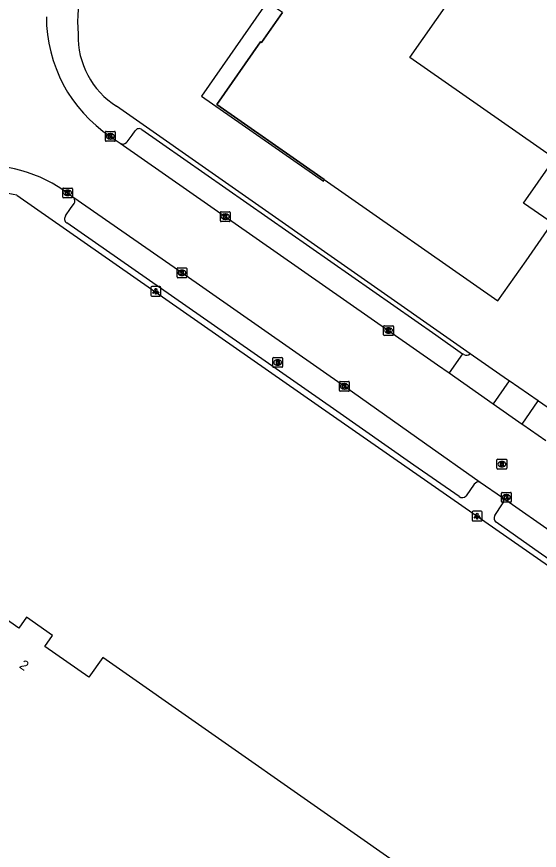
# Model space of a CAD drawing. Extents: x 155018 to 156648, y 383980 to 385733.
# Drawn here: x 155212.6 to 155265.9, y 385106.9 to 385192.1 of the extents above; entities that cross this region are included whole.
import ezdxf

# ---------------------------------------------------------------- set-up
doc = ezdxf.new("R2010")
doc.units = 0
for name, color, linetype in [('IMGEO_Brandkraan', 7, 'Continuous'), ('IMGEO_Kolk', 7, 'Continuous'), ('IMGEO_Lichtpunt', 7, 'Continuous'), ('IMGEO_Pand', 7, 'Continuous'), ('IMGEO_Pand_nummerreeks', 7, 'Continuous'), ('IMGEO_Pand_overbouw', 7, 'Continuous'), ('IMGEO_Rijbaan_lokaal_gesloten', 7, 'Continuous'), ('IMGEO_Rijbaan_lokaal_open', 7, 'Continuous'), ('IMGEO_Rioolput', 7, 'Continuous'), ('IMGEO_Voetpad_open', 7, 'Continuous')]:
    doc.layers.add(name, color=color, linetype=linetype)

msp = doc.modelspace()

# ---------------------------------------------------------------- linework, layer by layer
at = {"layer": 'IMGEO_Brandkraan'}
for p, q in [((155238.704, 385156.347), (155238.704, 385157.199)), ((155238.779, 385157.273), (155239.631, 385157.273)), ((155239.705, 385157.199), (155239.705, 385156.347)), ((155239.215, 385156.493), (155239.19, 385156.493)), ((155239.192, 385157.053), (155239.217, 385157.053)), ((155239.631, 385156.273), (155238.779, 385156.273))]:
    msp.add_line(p, q, dxfattribs=at)
for points in [[(155238.704, 385156.347), (155238.704, 385157.199)], [(155238.779, 385157.273), (155239.631, 385157.273)], [(155239.705, 385157.199), (155239.705, 385156.347)], [(155239.052, 385156.973), (155239.052, 385156.573), (155239.265, 385156.573)], [(155239.283, 385156.973), (155239.052, 385156.973)], [(155239.231, 385156.892), (155239.177, 385156.892), (155239.177, 385156.816)], [(155239.177, 385156.816), (155239.23, 385156.816)], [(155239.239, 385156.74), (155239.177, 385156.74), (155239.177, 385156.659)], [(155239.177, 385156.659), (155239.239, 385156.659)], [(155239.631, 385156.273), (155238.779, 385156.273)]]:
    msp.add_lwpolyline(points, dxfattribs=at)
for centre, radius, start, end in [((155238.781, 385157.197), 0.0765, 91.55205, 178.44795), ((155238.781, 385157.197), 0.0765, 91.55205, 178.44795), ((155239.629, 385157.197), 0.0765, 1.55205, 88.44795), ((155239.629, 385157.197), 0.0765, 1.55205, 88.44795), ((155238.781, 385156.349), 0.0765, 181.55205, 268.44795), ((155238.781, 385156.349), 0.0765, 181.55205, 268.44795), ((155239.232, 385156.854), 0.0379, 267.82845, 90.93552), ((155239.24, 385156.699), 0.0404, 269.87594, 90.50774), ((155239.271, 385156.824), 0.251, 268.66757, 293.53466), ((155239.287, 385156.828), 0.145, 59.4692, 91.53667), ((155239.312, 385156.875), 0.0922, 285.51372, 58.15012), ((155239.317, 385156.683), 0.105, 301.31148, 78.98903), ((155239.629, 385156.349), 0.0765, 271.55205, 358.44795), ((155239.629, 385156.349), 0.0765, 271.55205, 358.44795)]:
    msp.add_arc(centre, radius, start, end, dxfattribs=at)
for centre, major_axis, ratio, start_param, end_param in [((155239.191, 385156.773), (-0.387, 0.002), 0.722429, 4.712389, 7.853982), ((155239.216, 385156.773), (-0.39, 0.002), 0.717154, 1.570796, 4.712389)]:
    msp.add_ellipse(centre, major_axis=major_axis, ratio=ratio, start_param=start_param, end_param=end_param, dxfattribs=at)
at = {"layer": 'IMGEO_Kolk'}
for p, q in [((155221.621, 385179.436), (155221.621, 385180.288)), ((155221.696, 385180.362), (155222.548, 385180.362)), ((155222.622, 385180.288), (155222.622, 385179.436)), ((155222.548, 385179.362), (155221.696, 385179.362)), ((155222.132, 385179.582), (155222.107, 385179.582)), ((155222.109, 385180.142), (155222.134, 385180.142)), ((155217.256, 385173.657), (155217.256, 385174.509)), ((155217.331, 385174.583), (155218.183, 385174.583)), ((155217.744, 385174.363), (155217.769, 385174.363)), ((155218.257, 385174.509), (155218.257, 385173.657)), ((155218.183, 385173.583), (155217.331, 385173.583)), ((155217.767, 385173.803), (155217.742, 385173.803)), ((155233.352, 385171.233), (155233.352, 385172.085)), ((155233.427, 385172.159), (155234.279, 385172.159)), ((155233.84, 385171.939), (155233.865, 385171.939)), ((155234.353, 385172.085), (155234.353, 385171.233)), ((155234.279, 385171.159), (155233.427, 385171.159)), ((155233.863, 385171.379), (155233.838, 385171.379)), ((155228.932, 385165.499), (155228.932, 385166.351)), ((155229.007, 385166.425), (155229.859, 385166.425)), ((155229.42, 385166.205), (155229.445, 385166.205)), ((155229.933, 385166.351), (155229.933, 385165.499)), ((155229.859, 385165.425), (155229.007, 385165.425)), ((155229.443, 385165.645), (155229.418, 385165.645)), ((155250.022, 385159.597), (155250.022, 385160.449)), ((155250.097, 385160.523), (155250.949, 385160.523)), ((155250.533, 385159.743), (155250.508, 385159.743)), ((155250.51, 385160.303), (155250.535, 385160.303)), ((155251.023, 385160.449), (155251.023, 385159.597)), ((155250.949, 385159.523), (155250.097, 385159.523)), ((155245.512, 385153.905), (155245.512, 385154.757)), ((155245.587, 385154.831), (155246.439, 385154.831)), ((155246.513, 385154.757), (155246.513, 385153.905)), ((155246.439, 385153.831), (155245.587, 385153.831)), ((155246.023, 385154.051), (155245.998, 385154.051)), ((155246, 385154.611), (155246.025, 385154.611)), ((155262.05, 385142.569), (155262.05, 385143.421)), ((155262.125, 385143.495), (155262.977, 385143.495)), ((155262.561, 385142.715), (155262.536, 385142.715)), ((155262.538, 385143.275), (155262.563, 385143.275)), ((155263.051, 385143.421), (155263.051, 385142.569)), ((155262.977, 385142.495), (155262.125, 385142.495))]:
    msp.add_line(p, q, dxfattribs=at)
for points in [[(155221.621, 385179.436), (155221.621, 385180.288)], [(155221.696, 385180.362), (155222.548, 385180.362)], [(155222.622, 385180.288), (155222.622, 385179.436)], [(155222.548, 385179.362), (155221.696, 385179.362)], [(155221.942, 385180.062), (155222.065, 385180.062), (155222.065, 385179.911), (155222.195, 385180.062), (155222.359, 385180.062), (155222.213, 385179.911), (155222.366, 385179.662), (155222.214, 385179.662), (155222.129, 385179.826), (155222.065, 385179.759), (155222.065, 385179.662), (155221.942, 385179.662), (155221.942, 385180.062)], [(155217.256, 385173.657), (155217.256, 385174.509)], [(155217.331, 385174.583), (155218.183, 385174.583)], [(155217.577, 385174.283), (155217.7, 385174.283), (155217.7, 385174.132), (155217.83, 385174.283), (155217.994, 385174.283), (155217.848, 385174.132), (155218.001, 385173.883), (155217.849, 385173.883), (155217.764, 385174.047), (155217.7, 385173.98), (155217.7, 385173.883), (155217.577, 385173.883), (155217.577, 385174.283)], [(155218.257, 385174.509), (155218.257, 385173.657)], [(155218.183, 385173.583), (155217.331, 385173.583)], [(155233.352, 385171.233), (155233.352, 385172.085)], [(155233.427, 385172.159), (155234.279, 385172.159)], [(155233.673, 385171.859), (155233.796, 385171.859), (155233.796, 385171.708), (155233.926, 385171.859), (155234.09, 385171.859), (155233.944, 385171.708), (155234.097, 385171.459), (155233.945, 385171.459), (155233.86, 385171.623), (155233.796, 385171.556), (155233.796, 385171.459), (155233.673, 385171.459), (155233.673, 385171.859)], [(155234.353, 385172.085), (155234.353, 385171.233)], [(155234.279, 385171.159), (155233.427, 385171.159)], [(155228.932, 385165.499), (155228.932, 385166.351)], [(155229.007, 385166.425), (155229.859, 385166.425)], [(155229.253, 385166.125), (155229.376, 385166.125), (155229.376, 385165.974), (155229.506, 385166.125), (155229.67, 385166.125), (155229.524, 385165.974), (155229.677, 385165.725), (155229.525, 385165.725), (155229.44, 385165.889), (155229.376, 385165.822), (155229.376, 385165.725), (155229.253, 385165.725), (155229.253, 385166.125)], [(155229.933, 385166.351), (155229.933, 385165.499)], [(155229.859, 385165.425), (155229.007, 385165.425)], [(155250.022, 385159.597), (155250.022, 385160.449)], [(155250.097, 385160.523), (155250.949, 385160.523)], [(155250.343, 385160.223), (155250.466, 385160.223), (155250.466, 385160.072), (155250.596, 385160.223), (155250.76, 385160.223), (155250.614, 385160.072), (155250.767, 385159.823), (155250.615, 385159.823), (155250.53, 385159.987), (155250.466, 385159.92), (155250.466, 385159.823), (155250.343, 385159.823), (155250.343, 385160.223)], [(155251.023, 385160.449), (155251.023, 385159.597)], [(155250.949, 385159.523), (155250.097, 385159.523)], [(155245.512, 385153.905), (155245.512, 385154.757)], [(155245.587, 385154.831), (155246.439, 385154.831)], [(155246.513, 385154.757), (155246.513, 385153.905)], [(155246.439, 385153.831), (155245.587, 385153.831)], [(155245.833, 385154.531), (155245.956, 385154.531), (155245.956, 385154.38), (155246.086, 385154.531), (155246.25, 385154.531), (155246.104, 385154.38), (155246.257, 385154.131), (155246.105, 385154.131), (155246.02, 385154.295), (155245.956, 385154.228), (155245.956, 385154.131), (155245.833, 385154.131), (155245.833, 385154.531)], [(155262.05, 385142.569), (155262.05, 385143.421)], [(155262.125, 385143.495), (155262.977, 385143.495)], [(155262.371, 385143.195), (155262.494, 385143.195), (155262.494, 385143.044), (155262.624, 385143.195), (155262.788, 385143.195), (155262.642, 385143.044), (155262.795, 385142.795), (155262.643, 385142.795), (155262.558, 385142.959), (155262.494, 385142.892), (155262.494, 385142.795), (155262.371, 385142.795), (155262.371, 385143.195)], [(155263.051, 385143.421), (155263.051, 385142.569)], [(155262.977, 385142.495), (155262.125, 385142.495)]]:
    msp.add_lwpolyline(points, dxfattribs=at)
for centre, start, end in [((155221.698, 385180.286), 91.55205, 178.44795), ((155221.698, 385180.286), 91.55205, 178.44795), ((155222.546, 385180.286), 1.55205, 88.44795), ((155222.546, 385180.286), 1.55205, 88.44795), ((155221.698, 385179.438), 181.55205, 268.44795), ((155221.698, 385179.438), 181.55205, 268.44795), ((155222.546, 385179.438), 271.55205, 358.44795), ((155222.546, 385179.438), 271.55205, 358.44795), ((155217.333, 385174.507), 91.55205, 178.44795), ((155217.333, 385174.507), 91.55205, 178.44795), ((155218.181, 385174.507), 1.55205, 88.44795), ((155218.181, 385174.507), 1.55205, 88.44795), ((155217.333, 385173.659), 181.55205, 268.44795), ((155217.333, 385173.659), 181.55205, 268.44795), ((155218.181, 385173.659), 271.55205, 358.44795), ((155218.181, 385173.659), 271.55205, 358.44795), ((155233.429, 385172.083), 91.55205, 178.44795), ((155233.429, 385172.083), 91.55205, 178.44795), ((155234.277, 385172.083), 1.55205, 88.44795), ((155234.277, 385172.083), 1.55205, 88.44795), ((155233.429, 385171.235), 181.55205, 268.44795), ((155233.429, 385171.235), 181.55205, 268.44795), ((155234.277, 385171.235), 271.55205, 358.44795), ((155234.277, 385171.235), 271.55205, 358.44795), ((155229.009, 385166.349), 91.55205, 178.44795), ((155229.009, 385166.349), 91.55205, 178.44795), ((155229.857, 385166.349), 1.55205, 88.44795), ((155229.857, 385166.349), 1.55205, 88.44795), ((155229.009, 385165.501), 181.55205, 268.44795), ((155229.009, 385165.501), 181.55205, 268.44795), ((155229.857, 385165.501), 271.55205, 358.44795), ((155229.857, 385165.501), 271.55205, 358.44795), ((155250.099, 385160.447), 91.55205, 178.44795), ((155250.099, 385160.447), 91.55205, 178.44795), ((155250.947, 385160.447), 1.55205, 88.44795), ((155250.947, 385160.447), 1.55205, 88.44795), ((155250.099, 385159.599), 181.55205, 268.44795), ((155250.099, 385159.599), 181.55205, 268.44795), ((155250.947, 385159.599), 271.55205, 358.44795), ((155250.947, 385159.599), 271.55205, 358.44795), ((155245.589, 385154.755), 91.55205, 178.44795), ((155245.589, 385154.755), 91.55205, 178.44795), ((155246.437, 385154.755), 1.55205, 88.44795), ((155246.437, 385154.755), 1.55205, 88.44795), ((155245.589, 385153.907), 181.55205, 268.44795), ((155245.589, 385153.907), 181.55205, 268.44795), ((155246.437, 385153.907), 271.55205, 358.44795), ((155246.437, 385153.907), 271.55205, 358.44795), ((155262.127, 385143.419), 91.55205, 178.44795), ((155262.127, 385143.419), 91.55205, 178.44795), ((155262.975, 385143.419), 1.55205, 88.44795), ((155262.975, 385143.419), 1.55205, 88.44795), ((155262.127, 385142.571), 181.55205, 268.44795), ((155262.127, 385142.571), 181.55205, 268.44795), ((155262.975, 385142.571), 271.55205, 358.44795), ((155262.975, 385142.571), 271.55205, 358.44795)]:
    msp.add_arc(centre, 0.0765, start, end, dxfattribs=at)
for centre, major_axis, ratio, start_param, end_param in [((155222.108, 385179.862), (-0.387, 0.002), 0.722429, 4.712389, 7.853982), ((155222.133, 385179.862), (-0.39, 0.002), 0.717154, 1.570796, 4.712389), ((155217.743, 385174.083), (-0.387, 0.002), 0.722429, 4.712389, 7.853982), ((155217.768, 385174.083), (-0.39, 0.002), 0.717154, 1.570796, 4.712389), ((155233.839, 385171.659), (-0.387, 0.002), 0.722429, 4.712389, 7.853982), ((155233.864, 385171.659), (-0.39, 0.002), 0.717154, 1.570796, 4.712389), ((155229.419, 385165.925), (-0.387, 0.002), 0.722429, 4.712389, 7.853982), ((155229.444, 385165.925), (-0.39, 0.002), 0.717154, 1.570796, 4.712389), ((155250.509, 385160.023), (-0.387, 0.002), 0.722429, 4.712389, 7.853982), ((155250.534, 385160.023), (-0.39, 0.002), 0.717154, 1.570796, 4.712389), ((155245.999, 385154.331), (-0.387, 0.002), 0.722429, 4.712389, 7.853982), ((155246.024, 385154.331), (-0.39, 0.002), 0.717154, 1.570796, 4.712389), ((155262.537, 385142.995), (-0.387, 0.002), 0.722429, 4.712389, 7.853982), ((155262.562, 385142.995), (-0.39, 0.002), 0.717154, 1.570796, 4.712389)]:
    msp.add_ellipse(centre, major_axis=major_axis, ratio=ratio, start_param=start_param, end_param=end_param, dxfattribs=at)
at = {"layer": 'IMGEO_Lichtpunt'}
for p, q in [((155226.273, 385164.437), (155226.273, 385163.63)), ((155226.273, 385164.437), (155226.273, 385163.63)), ((155227.175, 385164.532), (155226.367, 385164.532)), ((155227.175, 385164.532), (155226.367, 385164.532)), ((155227.269, 385163.63), (155227.269, 385164.437)), ((155227.269, 385163.63), (155227.269, 385164.437)), ((155226.367, 385163.536), (155227.175, 385163.536)), ((155226.367, 385163.536), (155227.175, 385163.536)), ((155259.076, 385141.48), (155259.076, 385140.673)), ((155259.076, 385141.48), (155259.076, 385140.673)), ((155259.978, 385141.575), (155259.17, 385141.575)), ((155259.978, 385141.575), (155259.17, 385141.575)), ((155260.072, 385140.673), (155260.072, 385141.48)), ((155260.072, 385140.673), (155260.072, 385141.48)), ((155259.17, 385140.579), (155259.978, 385140.579)), ((155259.17, 385140.579), (155259.978, 385140.579))]:
    msp.add_line(p, q, dxfattribs=at)
for points in [[(155226.647, 385164.101), (155226.686, 385164.073), (155226.498, 385163.811), (155226.46, 385163.838), (155226.647, 385164.101)], [(155226.749, 385164.053), (155226.796, 385164.053), (155226.796, 385163.731), (155226.749, 385163.731), (155226.749, 385164.053)], [(155226.859, 385164.073), (155226.897, 385164.1), (155227.084, 385163.838), (155227.045, 385163.81), (155226.859, 385164.073)], [(155259.45, 385141.144), (155259.489, 385141.116), (155259.301, 385140.854), (155259.263, 385140.881), (155259.45, 385141.144)], [(155259.552, 385141.096), (155259.599, 385141.096), (155259.599, 385140.774), (155259.552, 385140.774), (155259.552, 385141.096)], [(155259.662, 385141.116), (155259.7, 385141.143), (155259.887, 385140.881), (155259.848, 385140.853), (155259.662, 385141.116)]]:
    msp.add_lwpolyline(points, dxfattribs=at)
for centre in [(155226.772, 385164.235), (155259.575, 385141.278)]:
    msp.add_circle(centre, 0.0994, dxfattribs=at)
for centre, start, end in [((155226.367, 385164.437), 90, 180), ((155226.367, 385164.437), 90, 180), ((155227.175, 385164.437), 0, 90), ((155227.175, 385164.437), 0, 90), ((155226.367, 385163.63), 180, 270), ((155226.367, 385163.63), 180, 270), ((155227.175, 385163.63), 270, 0), ((155227.175, 385163.63), 270, 360), ((155259.17, 385141.48), 90, 180), ((155259.17, 385141.48), 90, 180), ((155259.978, 385141.48), 0, 90), ((155259.978, 385141.48), 0, 90), ((155259.17, 385140.673), 180, 270), ((155259.17, 385140.673), 180, 270), ((155259.978, 385140.673), 270, 0), ((155259.978, 385140.673), 270, 360)]:
    msp.add_arc(centre, 0.0946, start, end, dxfattribs=at)
at = {"layer": 'IMGEO_Pand'}
for points in [[(155267.482, 385177.596), (155252.705, 385187.911), (155264.94, 385205.414), (155264.104, 385210.198), (155263.883, 385211.443), (155262.053, 385221.658), (155261.666, 385223.9)], [(155239.686, 385192.493), (155237.564, 385189.452), (155237.457, 385189.526), (155232.988, 385183.122), (155243.955, 385175.442), (155261.694, 385163.069), (155264.564, 385167.164), (155267.337, 385171.123)], [(155266.918, 385171.222), (155264.306, 385173.046), (155267.305, 385177.342)], [(155254.387, 385103.495), (155221.346, 385126.646), (155219.941, 385124.629), (155215.431, 385127.769), (155216.213, 385128.892), (155213.548, 385130.747), (155212.777, 385129.64), (155209.759, 385131.74)]]:
    msp.add_lwpolyline(points, dxfattribs=at)
at = {"layer": 'IMGEO_Pand_overbouw'}
msp.add_lwpolyline([(155243.955, 385175.442), (155232.988, 385183.122), (155237.457, 385189.526), (155237.564, 385189.452), (155239.686, 385192.493), (155239.088, 385192.912), (155239.215, 385193.093), (155239.314, 385193.025), (155240.207, 385194.305), (155240.109, 385194.374), (155240.236, 385194.555), (155240.827, 385194.143), (155241.444, 385195.029), (155239.875, 385196.125), (155231.414, 385183.979), (155243.87, 385175.274)], close=True, dxfattribs=at)
at = {"layer": 'IMGEO_Rijbaan_lokaal_gesloten'}
for points in [[(155222.117, 385179.862), (155223.128, 385179.156)], [(155223.128, 385179.156), (155255.535, 385156.517), (155256.698, 385155.702)], [(155218.393, 385173.569), (155218.227, 385173.684), (155217.756, 385174.082), (155216.784, 385174.718)], [(155259.887, 385144.522), (155254.18, 385148.516), (155246.012, 385154.33), (155229.432, 385165.924), (155218.393, 385173.569)], [(155256.698, 385155.702), (155261.211, 385152.54)], [(155261.211, 385152.54), (155264.152, 385150.479)], [(155264.152, 385150.479), (155264.222, 385150.43), (155266.572, 385148.784)], [(155262.142, 385142.929), (155259.887, 385144.522)], [(155276.485, 385133.016), (155267.693, 385139.068), (155262.142, 385142.929)]]:
    msp.add_lwpolyline(points, dxfattribs=at)
for centre, radius, start, end in [((155230.252, 385192.058), 14.66, 179.90113, 236.2959), ((155209.045, 385162.179), 14.735, 58.31604, 101.23019)]:
    msp.add_arc(centre, radius, start, end, dxfattribs=at)
at = {"layer": 'IMGEO_Rijbaan_lokaal_open'}
for points in [[(155258.077, 385157.664), (155256.698, 385155.702)], [(155258.215, 385157.583), (155258.077, 385157.664)], [(155262.841, 385154.876), (155262.655, 385155.005), (155258.844, 385157.636)], [(155262.841, 385154.876), (155261.211, 385152.54)], [(155264.152, 385150.479), (155265.783, 385152.847)], [(155268.248, 385151.145), (155265.84, 385152.807), (155265.783, 385152.847)]]:
    msp.add_lwpolyline(points, dxfattribs=at)
msp.add_arc((155258.497, 385158), 0.503, 235.97919, 313.65362, dxfattribs=at)
at = {"layer": 'IMGEO_Rioolput'}
for p, q in [((155261.595, 385145.96), (155261.595, 385146.812)), ((155261.67, 385146.886), (155262.522, 385146.886)), ((155262.083, 385146.666), (155262.108, 385146.666)), ((155262.596, 385146.812), (155262.596, 385145.96)), ((155262.522, 385145.886), (155261.67, 385145.886)), ((155262.106, 385146.106), (155262.081, 385146.106))]:
    msp.add_line(p, q, dxfattribs=at)
for points in [[(155261.595, 385145.96), (155261.595, 385146.812)], [(155261.67, 385146.886), (155262.522, 385146.886)], [(155262.184, 385146.584), (155261.932, 385146.586), (155261.932, 385146.186)], [(155261.932, 385146.186), (155262.056, 385146.186), (155262.056, 385146.348), (155262.067, 385146.348)], [(155262.11, 385146.505), (155262.056, 385146.505), (155262.056, 385146.424)], [(155262.056, 385146.424), (155262.108, 385146.424)], [(155262.114, 385146.319), (155262.185, 385146.186), (155262.325, 385146.186), (155262.26, 385146.312)], [(155262.596, 385146.812), (155262.596, 385145.96)], [(155262.522, 385145.886), (155261.67, 385145.886)]]:
    msp.add_lwpolyline(points, dxfattribs=at)
for centre, radius, start, end in [((155261.672, 385146.81), 0.0765, 91.55205, 178.44795), ((155261.672, 385146.81), 0.0765, 91.55205, 178.44795), ((155262.066, 385146.295), 0.0533, 26.02933, 88.69889), ((155262.092, 385146.613), 0.19, 274.7715, 282.96867), ((155262.116, 385146.409), 0.0964, 77.00612, 93.18647), ((155262.13, 385146.466), 0.0378, 276.66336, 79.67722), ((155262.183, 385146.474), 0.109, 350.36119, 89.41601), ((155262.181, 385146.474), 0.112, 277.58423, 350.98172), ((155262.165, 385146.259), 0.108, 29.51342, 73.79051), ((155262.52, 385146.81), 0.0765, 1.55205, 88.44795), ((155262.52, 385146.81), 0.0765, 1.55205, 88.44795), ((155261.672, 385145.962), 0.0765, 181.55205, 268.44795), ((155261.672, 385145.962), 0.0765, 181.55205, 268.44795), ((155262.52, 385145.962), 0.0765, 271.55205, 358.44795), ((155262.52, 385145.962), 0.0765, 271.55205, 358.44795)]:
    msp.add_arc(centre, radius, start, end, dxfattribs=at)
for centre, major_axis, ratio, start_param, end_param in [((155262.082, 385146.386), (-0.387, 0.002), 0.722429, 4.712389, 7.853982), ((155262.107, 385146.386), (-0.39, 0.002), 0.717154, 1.570796, 4.712389)]:
    msp.add_ellipse(centre, major_axis=major_axis, ratio=ratio, start_param=start_param, end_param=end_param, dxfattribs=at)
at = {"layer": 'IMGEO_Voetpad_open'}
for points in [[(155258.844, 385157.636), (155222.76, 385182.932)], [(155223.756, 385179.218), (155223.827, 385179.302), (155224.334, 385179.971), (155224.65, 385180.43)], [(155225.351, 385180.555), (155255.364, 385159.573), (155258.077, 385157.664)], [(155212.561, 385173.841), (155243.348, 385152.362), (155276.133, 385129.546)], [(155217.556, 385171.732), (155218.069, 385172.492), (155218.428, 385172.991)], [(155257.74, 385143.063), (155253.122, 385146.285), (155244.896, 385152.043), (155217.667, 385171.034)], [(155265.783, 385152.847), (155262.841, 385154.876)], [(155259.274, 385144.324), (155258.444, 385143.148)], [(155261.385, 385141.139), (155262.174, 385142.324)], [(155276.226, 385129.93), (155276.03, 385130.271), (155265.448, 385137.677), (155261.512, 385140.441)]]:
    msp.add_lwpolyline(points, dxfattribs=at)
for centre, radius, start, end in [((155232.662, 385191.555), 13.878, 143.282, 185.17147), ((155227.224, 385190.033), 8.388, 178.14877, 237.842), ((155225.06, 385180.156), 0.493, 53.91834, 146.30271), ((155223.402, 385179.589), 0.513, 237.6663, 313.61034), ((155209.054, 385159.198), 15.057, 76.52967, 98.67369), ((155218.054, 385173.258), 0.46, 324.41334, 42.51713), ((155217.917, 385171.432), 0.469, 140.19372, 237.87797), ((155259.695, 385144.068), 0.493, 67.12697, 148.67411), ((155258.047, 385143.476), 0.515, 233.36468, 320.4043), ((155261.77, 385142.606), 0.493, 325.0816, 40.97379), ((155261.791, 385140.852), 0.497, 144.75262, 235.87152)]:
    msp.add_arc(centre, radius, start, end, dxfattribs=at)

# ---------------------------------------------------------------- texts
at = {"layer": 'IMGEO_Pand_nummerreeks'}
msp.add_text('2', height=1, rotation=325.07249, dxfattribs=at).set_placement((155212.745, 385125.654))

doc.saveas('drawing.dxf')
